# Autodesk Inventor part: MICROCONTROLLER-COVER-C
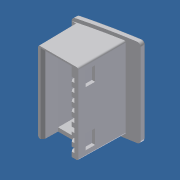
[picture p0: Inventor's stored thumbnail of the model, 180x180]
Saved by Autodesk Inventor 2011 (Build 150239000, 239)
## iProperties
Created: 2008-01
Part Number: MICROCONTROLLER-COVER-C
Document SubType Name: Modeling
Density: 1 g/cm^3
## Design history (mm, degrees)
feature "Base1"
body "Solid1"
